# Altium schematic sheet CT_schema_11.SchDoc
size 274 x 160 mm
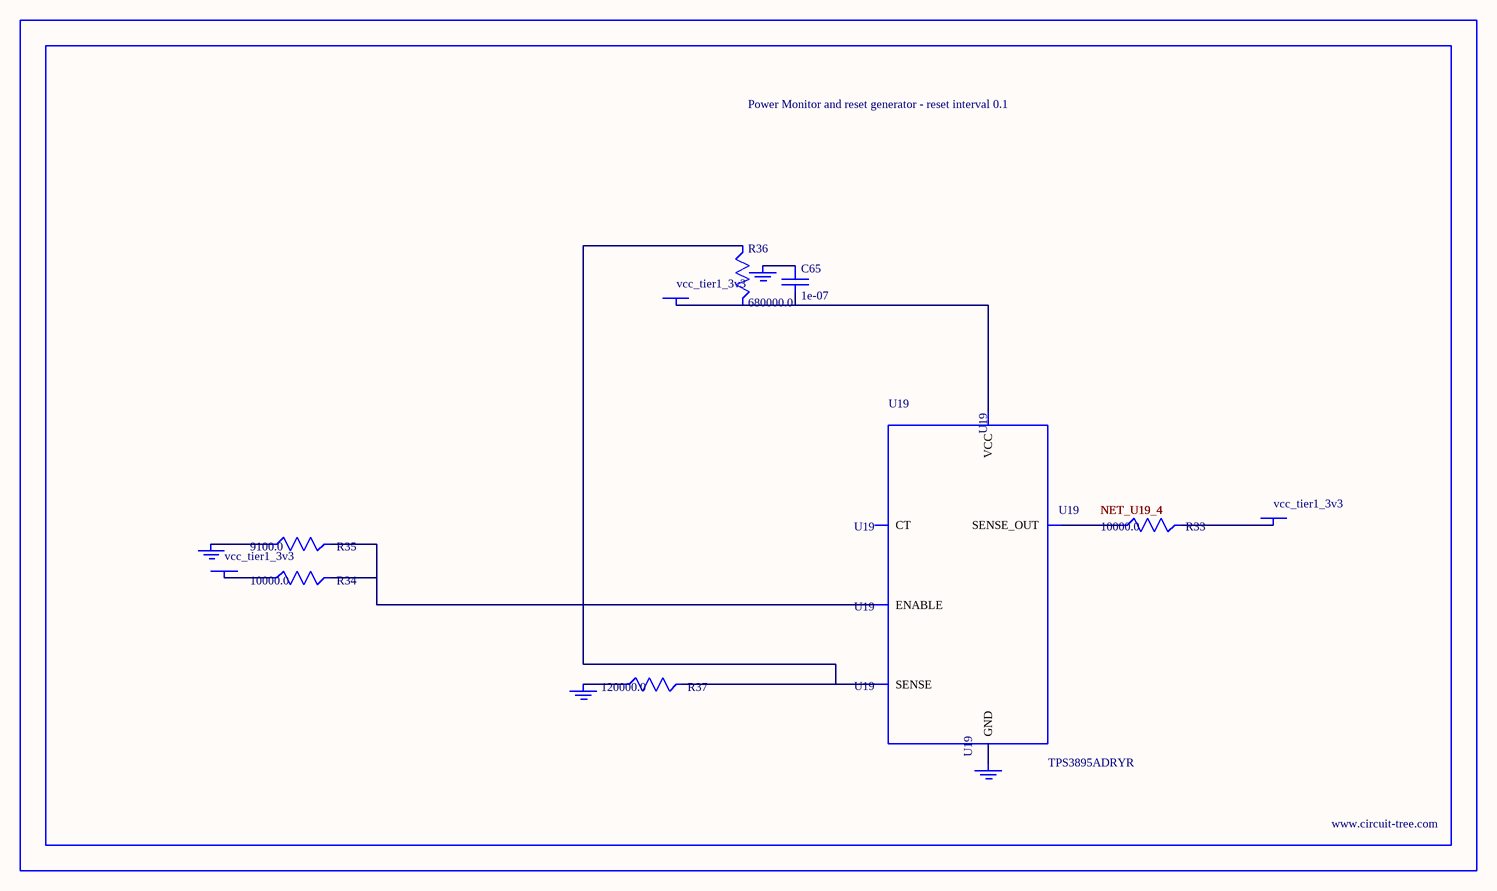
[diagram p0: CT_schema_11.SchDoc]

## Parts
BORDER10  (no value)
C65  1e-07  [C0402]
GND_INSTANCE_10_0  (no value)
GND_INSTANCE_10_1  (no value)
GND_INSTANCE_10_2  (no value)
GND_INSTANCE_10_3  (no value)
POWER_INSTANCE_10_0  vcc_tier1_3v3
POWER_INSTANCE_10_1  vcc_tier1_3v3
POWER_INSTANCE_10_2  vcc_tier1_3v3
R33  10000.0  [R0603]
R34  10000.0  [R0603]
R35  9100.0  [R0603]
R36  680000.0  [R0603]
R37  120000.0  [R0603]
U19  TPS3895ADRYR  [SON-6]

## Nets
NetC65_1: C65.1 GND_INSTANCE_10_2.0(GND)
NetC65_2: C65.2 POWER_INSTANCE_10_2.0(PWR) R36.2 U19.6(VCC)
NetGND_INSTANCE_10_0_0: GND_INSTANCE_10_0.0(GND) R35.1
NetGND_INSTANCE_10_1_0: GND_INSTANCE_10_1.0(GND) R37.1
NetGND_INSTANCE_10_3_0: GND_INSTANCE_10_3.0(GND) U19.2(GND)
NetPOWER_INSTANCE_10_0_0: POWER_INSTANCE_10_0.0(PWR) R34.1
NetPOWER_INSTANCE_10_1_0: POWER_INSTANCE_10_1.0(PWR) R33.2
NetR33_1: R33.1 U19.4(SENSE_OUT)
NetR34_2: R34.2 R35.2 U19.1(ENABLE)
NetR36_1: R36.1 R37.2 U19.3(SENSE)

Not connected (* = marked no-connect by the designer): U19 5(CT)

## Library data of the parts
BORDER10 = BORDER_PAGE10
C65 = C0402C104K3RACTU
GND_INSTANCE_10_0-GND_INSTANCE_10_3 = GND
POWER_INSTANCE_10_0-POWER_INSTANCE_10_2 = PWR
R33 R34 = RC0603JR-0710KL
R35 = RC0603JR-079K1L
R36 = RC0603JR-07680KL
R37 = RC0603JR-07120KL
